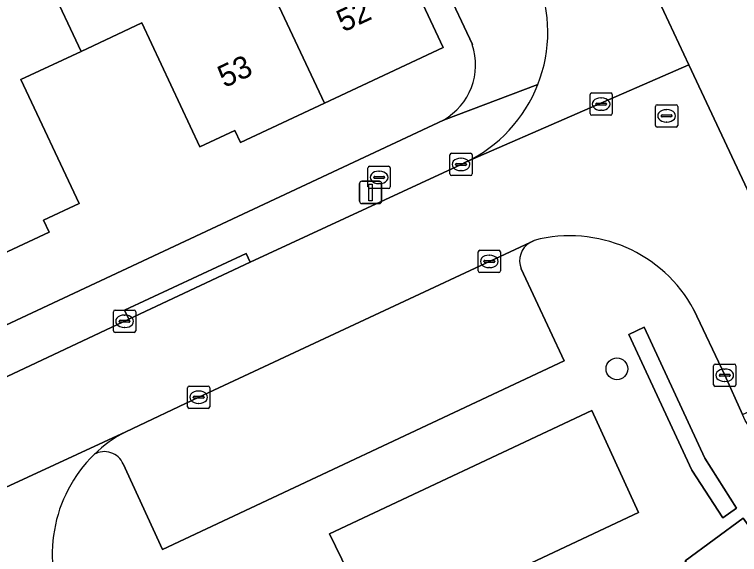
# Model space of a CAD drawing. Extents: x 162879 to 165540, y 384011 to 385181.
# Drawn here: x 163874.48 to 163907.06, y 384315.4 to 384339.68 of the extents above; entities that cross this region are included whole.
import ezdxf

# ---------------------------------------------------------------- set-up
doc = ezdxf.new("R2010")
doc.units = 0
for name, color, linetype in [('IMGEO_Boom', 7, 'Continuous'), ('IMGEO_Brandkraan', 7, 'Continuous'), ('IMGEO_Erf', 7, 'Continuous'), ('IMGEO_Groenvoorziening', 7, 'Continuous'), ('IMGEO_Haag', 7, 'Continuous'), ('IMGEO_Kolk', 7, 'Continuous'), ('IMGEO_Lichtmast', 7, 'Continuous'), ('IMGEO_Pand', 7, 'Continuous'), ('IMGEO_Pand_nummerreeks', 7, 'Continuous'), ('IMGEO_Parkeervlak_open', 7, 'Continuous'), ('IMGEO_Rijbaan_lokaal_gesloten', 7, 'Continuous'), ('IMGEO_Rioolput', 7, 'Continuous'), ('IMGEO_Voetpad_open', 7, 'Continuous')]:
    doc.layers.add(name, color=color, linetype=linetype)

msp = doc.modelspace()

# ---------------------------------------------------------------- linework, layer by layer
at = {"layer": 'IMGEO_Boom'}
msp.add_circle((163901.554, 384323.751), 0.489, dxfattribs=at)
at = {"layer": 'IMGEO_Brandkraan'}
for p, q in [((163890.443, 384332.857), (163891.295, 384332.857)), ((163890.368, 384331.931), (163890.368, 384332.783)), ((163890.856, 384332.637), (163890.881, 384332.637)), ((163891.369, 384332.783), (163891.369, 384331.931)), ((163890.627, 384332.351), (163890.627, 384332.363)), ((163891.065, 384332.314), (163890.667, 384332.314)), ((163890.67, 384332.4), (163891.068, 384332.4)), ((163891.111, 384332.363), (163891.111, 384332.351)), ((163890.879, 384332.077), (163890.854, 384332.077)), ((163891.295, 384331.857), (163890.443, 384331.857))]:
    msp.add_line(p, q, dxfattribs=at)
for points in [[(163890.443, 384332.857), (163891.295, 384332.857)], [(163890.368, 384331.931), (163890.368, 384332.783)], [(163891.369, 384332.783), (163891.369, 384331.931)], [(163891.295, 384331.857), (163890.443, 384331.857)]]:
    msp.add_lwpolyline(points, dxfattribs=at)
for centre, radius, start, end in [((163890.445, 384332.781), 0.0765, 91.552, 178.448), ((163890.445, 384332.781), 0.0765, 91.552, 178.448), ((163891.293, 384332.781), 0.0765, 1.552, 88.448), ((163891.293, 384332.781), 0.0765, 1.552, 88.448), ((163890.667, 384332.36), 0.0403, 85.8775, 175.7526), ((163890.664, 384332.35), 0.0366, 178.938, 274.7102), ((163891.068, 384332.357), 0.043, 264.8664, 352.4533), ((163891.072, 384332.362), 0.0386, 1.7309, 96.639), ((163890.445, 384331.933), 0.0765, 181.552, 268.448), ((163890.445, 384331.933), 0.0765, 181.552, 268.448), ((163891.293, 384331.933), 0.0765, 271.552, 358.448), ((163891.293, 384331.933), 0.0765, 271.552, 358.448)]:
    msp.add_arc(centre, radius, start, end, dxfattribs=at)
for centre, major_axis, ratio, start_param, end_param in [((163890.855, 384332.357), (-0.387, 0.002), 0.722429, 4.712389, 7.853982), ((163890.88, 384332.357), (-0.39, 0.002), 0.717154, 1.570796, 4.712389)]:
    msp.add_ellipse(centre, major_axis=major_axis, ratio=ratio, start_param=start_param, end_param=end_param, dxfattribs=at)
at = {"layer": 'IMGEO_Erf'}
for points in [[(163895.057, 384338.324), (163890.087, 384348.891), (163886.367, 384356.8), (163879.926, 384353.788), (163880.083, 384353.451), (163875.891, 384351.499), (163874.656, 384354.151), (163878.848, 384356.103), (163878.614, 384356.605), (163863.373, 384349.478), (163861.138, 384348.883), (163861.827, 384346.296), (163857.881, 384345.245), (163857.193, 384347.833), (163844.072, 384344.341), (163843.714, 384345.683), (163846.774, 384346.497), (163846.073, 384349.131), (163849.929, 384350.156)], [(163888.982, 384348.374), (163893.752, 384338.19), (163888.413, 384335.69), (163884.645, 384333.926), (163884.391, 384334.47), (163882.806, 384333.727), (163880.198, 384339.298), (163877.472, 384338.021), (163874.764, 384336.753), (163877.382, 384331.186), (163875.787, 384330.441), (163876.041, 384329.897), (163872.318, 384328.154), (163872.102, 384328.053), (163871.848, 384328.597), (163870.707, 384328.063), (163870.961, 384327.518), (163867.129, 384325.724), (163861.777, 384323.218), (163858.915, 384329.331), (163855.03, 384328.471), (163851.161, 384327.615)], [(163863.881, 384320.929), (163893.758, 384334.936)]]:
    msp.add_lwpolyline(points, dxfattribs=at)
msp.add_arc((163892.34, 384337.423), 2.862, 299.6881, 18.3571, dxfattribs=at)
at = {"layer": 'IMGEO_Groenvoorziening'}
for points in [[(163906.317, 384317.059), (163906.927, 384317.485), (163905.499, 384319.74), (163902.771, 384325.619), (163902.093, 384325.298), (163904.927, 384319.193)], [(163906.525, 384312.54), (163909.096, 384314.438), (163907.232, 384317.04), (163904.624, 384315.125)]]:
    msp.add_lwpolyline(points, close=True, dxfattribs=at)
at = {"layer": 'IMGEO_Haag'}
msp.add_lwpolyline([(163906.317, 384317.059), (163906.927, 384317.485), (163905.499, 384319.74), (163902.771, 384325.619), (163902.093, 384325.298), (163904.927, 384319.193)], close=True, dxfattribs=at)
at = {"layer": 'IMGEO_Kolk'}
for p, q in [((163894.048, 384332.514), (163894.048, 384333.366)), ((163894.123, 384333.44), (163894.975, 384333.44)), ((163894.536, 384333.22), (163894.561, 384333.22)), ((163895.049, 384333.366), (163895.049, 384332.514)), ((163894.307, 384332.934), (163894.307, 384332.946)), ((163894.745, 384332.897), (163894.347, 384332.897)), ((163894.35, 384332.983), (163894.748, 384332.983)), ((163894.791, 384332.946), (163894.791, 384332.934)), ((163894.559, 384332.66), (163894.534, 384332.66)), ((163894.975, 384332.44), (163894.123, 384332.44)), ((163895.319, 384328.155), (163895.319, 384329.007)), ((163895.394, 384329.081), (163896.246, 384329.081)), ((163896.32, 384329.007), (163896.32, 384328.155)), ((163895.621, 384328.624), (163896.019, 384328.624)), ((163895.807, 384328.861), (163895.832, 384328.861)), ((163895.578, 384328.575), (163895.578, 384328.587)), ((163896.016, 384328.538), (163895.618, 384328.538)), ((163895.83, 384328.301), (163895.805, 384328.301)), ((163896.062, 384328.587), (163896.062, 384328.575)), ((163896.246, 384328.081), (163895.394, 384328.081)), ((163879.005, 384326.389), (163879.857, 384326.389)), ((163878.93, 384325.463), (163878.93, 384326.315)), ((163879.418, 384326.169), (163879.443, 384326.169)), ((163879.931, 384326.315), (163879.931, 384325.463)), ((163879.189, 384325.883), (163879.189, 384325.895)), ((163879.627, 384325.846), (163879.229, 384325.846)), ((163879.232, 384325.932), (163879.63, 384325.932)), ((163879.673, 384325.895), (163879.673, 384325.883)), ((163879.857, 384325.389), (163879.005, 384325.389)), ((163879.441, 384325.609), (163879.416, 384325.609)), ((163905.897, 384323.036), (163905.897, 384323.888)), ((163905.972, 384323.962), (163906.824, 384323.962)), ((163906.385, 384323.742), (163906.41, 384323.742)), ((163906.898, 384323.888), (163906.898, 384323.036)), ((163906.156, 384323.456), (163906.156, 384323.468)), ((163906.594, 384323.419), (163906.196, 384323.419)), ((163906.199, 384323.505), (163906.597, 384323.505)), ((163906.64, 384323.468), (163906.64, 384323.456)), ((163906.408, 384323.182), (163906.383, 384323.182)), ((163882.259, 384322.049), (163882.259, 384322.901)), ((163882.334, 384322.975), (163883.186, 384322.975)), ((163882.747, 384322.755), (163882.772, 384322.755)), ((163883.26, 384322.901), (163883.26, 384322.049)), ((163906.824, 384322.962), (163905.972, 384322.962)), ((163882.518, 384322.469), (163882.518, 384322.481)), ((163882.956, 384322.432), (163882.558, 384322.432)), ((163882.561, 384322.518), (163882.959, 384322.518)), ((163883.002, 384322.481), (163883.002, 384322.469)), ((163882.77, 384322.195), (163882.745, 384322.195)), ((163883.186, 384321.975), (163882.334, 384321.975))]:
    msp.add_line(p, q, dxfattribs=at)
for points in [[(163894.048, 384332.514), (163894.048, 384333.366)], [(163894.123, 384333.44), (163894.975, 384333.44)], [(163895.049, 384333.366), (163895.049, 384332.514)], [(163894.975, 384332.44), (163894.123, 384332.44)], [(163895.319, 384328.155), (163895.319, 384329.007)], [(163895.394, 384329.081), (163896.246, 384329.081)], [(163896.32, 384329.007), (163896.32, 384328.155)], [(163896.246, 384328.081), (163895.394, 384328.081)], [(163879.005, 384326.389), (163879.857, 384326.389)], [(163878.93, 384325.463), (163878.93, 384326.315)], [(163879.931, 384326.315), (163879.931, 384325.463)], [(163879.857, 384325.389), (163879.005, 384325.389)], [(163905.897, 384323.036), (163905.897, 384323.888)], [(163905.972, 384323.962), (163906.824, 384323.962)], [(163906.898, 384323.888), (163906.898, 384323.036)], [(163882.259, 384322.049), (163882.259, 384322.901)], [(163882.334, 384322.975), (163883.186, 384322.975)], [(163883.26, 384322.901), (163883.26, 384322.049)], [(163906.824, 384322.962), (163905.972, 384322.962)], [(163883.186, 384321.975), (163882.334, 384321.975)]]:
    msp.add_lwpolyline(points, dxfattribs=at)
for centre, radius, start, end in [((163894.125, 384333.364), 0.0765, 91.552, 178.448), ((163894.125, 384333.364), 0.0765, 91.552, 178.448), ((163894.973, 384333.364), 0.0765, 1.552, 88.448), ((163894.973, 384333.364), 0.0765, 1.552, 88.448), ((163894.347, 384332.943), 0.0403, 85.8775, 175.7526), ((163894.344, 384332.933), 0.0366, 178.938, 274.7102), ((163894.748, 384332.94), 0.043, 264.8664, 352.4533), ((163894.752, 384332.945), 0.0386, 1.7309, 96.639), ((163894.125, 384332.516), 0.0765, 181.552, 268.448), ((163894.125, 384332.516), 0.0765, 181.552, 268.448), ((163894.973, 384332.516), 0.0765, 271.552, 358.448), ((163894.973, 384332.516), 0.0765, 271.552, 358.448), ((163895.396, 384329.005), 0.0765, 91.552, 178.448), ((163895.396, 384329.005), 0.0765, 91.552, 178.448), ((163896.244, 384329.005), 0.0765, 1.552, 88.448), ((163896.244, 384329.005), 0.0765, 1.552, 88.448), ((163895.618, 384328.584), 0.0403, 85.8775, 175.7526), ((163896.023, 384328.586), 0.0386, 1.7309, 96.639), ((163895.615, 384328.574), 0.0366, 178.938, 274.7102), ((163896.019, 384328.581), 0.043, 264.8664, 352.4533), ((163895.396, 384328.157), 0.0765, 181.552, 268.448), ((163895.396, 384328.157), 0.0765, 181.552, 268.448), ((163896.244, 384328.157), 0.0765, 271.552, 358.448), ((163896.244, 384328.157), 0.0765, 271.552, 358.448), ((163879.007, 384326.313), 0.0765, 91.552, 178.448), ((163879.007, 384326.313), 0.0765, 91.552, 178.448), ((163879.855, 384326.313), 0.0765, 1.552, 88.448), ((163879.855, 384326.313), 0.0765, 1.552, 88.448), ((163879.229, 384325.892), 0.0403, 85.8775, 175.7526), ((163879.226, 384325.882), 0.0366, 178.938, 274.7102), ((163879.63, 384325.889), 0.043, 264.8664, 352.4533), ((163879.634, 384325.894), 0.0386, 1.7309, 96.639), ((163879.007, 384325.465), 0.0765, 181.552, 268.448), ((163879.007, 384325.465), 0.0765, 181.552, 268.448), ((163879.855, 384325.465), 0.0765, 271.552, 358.448), ((163879.855, 384325.465), 0.0765, 271.552, 358.448), ((163905.974, 384323.886), 0.0765, 91.552, 178.448), ((163905.974, 384323.886), 0.0765, 91.552, 178.448), ((163906.822, 384323.886), 0.0765, 1.552, 88.448), ((163906.822, 384323.886), 0.0765, 1.552, 88.448), ((163906.196, 384323.465), 0.0403, 85.8775, 175.7526), ((163906.193, 384323.455), 0.0366, 178.938, 274.7102), ((163906.597, 384323.462), 0.043, 264.8664, 352.4533), ((163906.601, 384323.467), 0.0386, 1.7309, 96.639), ((163882.336, 384322.899), 0.0765, 91.552, 178.448), ((163882.336, 384322.899), 0.0765, 91.552, 178.448), ((163883.184, 384322.899), 0.0765, 1.552, 88.448), ((163883.184, 384322.899), 0.0765, 1.552, 88.448), ((163905.974, 384323.038), 0.0765, 181.552, 268.448), ((163905.974, 384323.038), 0.0765, 181.552, 268.448), ((163906.822, 384323.038), 0.0765, 271.552, 358.448), ((163906.822, 384323.038), 0.0765, 271.552, 358.448), ((163882.558, 384322.478), 0.0403, 85.8775, 175.7526), ((163882.555, 384322.468), 0.0366, 178.938, 274.7102), ((163882.959, 384322.475), 0.043, 264.8664, 352.4533), ((163882.963, 384322.48), 0.0386, 1.7309, 96.639), ((163882.336, 384322.051), 0.0765, 181.552, 268.448), ((163882.336, 384322.051), 0.0765, 181.552, 268.448), ((163883.184, 384322.051), 0.0765, 271.552, 358.448), ((163883.184, 384322.051), 0.0765, 271.552, 358.448)]:
    msp.add_arc(centre, radius, start, end, dxfattribs=at)
for centre, major_axis, ratio, start_param, end_param in [((163894.535, 384332.94), (-0.387, 0.002), 0.722429, 4.712389, 7.853982), ((163894.56, 384332.94), (-0.39, 0.002), 0.717154, 1.570796, 4.712389), ((163895.806, 384328.581), (-0.387, 0.002), 0.722429, 4.712389, 7.853982), ((163895.831, 384328.581), (-0.39, 0.002), 0.717154, 1.570796, 4.712389), ((163879.417, 384325.889), (-0.387, 0.002), 0.722429, 4.712389, 7.853982), ((163879.442, 384325.889), (-0.39, 0.002), 0.717154, 1.570796, 4.712389), ((163906.384, 384323.462), (-0.387, 0.002), 0.722429, 4.712389, 7.853982), ((163906.409, 384323.462), (-0.39, 0.002), 0.717154, 1.570796, 4.712389), ((163882.746, 384322.475), (-0.387, 0.002), 0.722429, 4.712389, 7.853982), ((163882.771, 384322.475), (-0.39, 0.002), 0.717154, 1.570796, 4.712389)]:
    msp.add_ellipse(centre, major_axis=major_axis, ratio=ratio, start_param=start_param, end_param=end_param, dxfattribs=at)
at = {"layer": 'IMGEO_Lichtmast'}
for p, q in [((163889.99, 384331.282), (163889.99, 384332.082)), ((163889.99, 384332.082), (163889.99, 384331.282)), ((163890.09, 384332.182), (163890.88, 384332.182)), ((163890.88, 384332.182), (163890.09, 384332.182)), ((163890.98, 384332.082), (163890.98, 384331.282)), ((163890.98, 384331.282), (163890.98, 384332.082)), ((163890.88, 384331.182), (163890.09, 384331.182)), ((163890.09, 384331.182), (163890.88, 384331.182))]:
    msp.add_line(p, q, dxfattribs=at)
msp.add_lwpolyline([(163890.41, 384332.057), (163890.56, 384332.057), (163890.56, 384331.307), (163890.41, 384331.307), (163890.41, 384332.057)], dxfattribs=at)
for centre, start, end in [((163890.09, 384332.082), 90, 180), ((163890.09, 384332.082), 90, 180), ((163890.88, 384332.082), 0, 90), ((163890.88, 384332.082), 360, 90), ((163890.09, 384331.282), 180, 270), ((163890.09, 384331.282), 180, 270), ((163890.88, 384331.282), 270, 0), ((163890.88, 384331.282), 270, 0)]:
    msp.add_arc(centre, 0.1, start, end, dxfattribs=at)
at = {"layer": 'IMGEO_Pand'}
for points in [[(163883.635, 384345.871), (163888.413, 384335.69), (163893.752, 384338.19), (163888.982, 384348.374)], [(163883.635, 384345.871), (163878.595, 384343.511), (163877.603, 384345.631), (163874.574, 384344.201), (163877.472, 384338.021), (163880.198, 384339.298), (163882.806, 384333.727), (163884.391, 384334.47), (163884.645, 384333.926), (163888.413, 384335.69)], [(163874.574, 384344.201), (163873.082, 384343.496), (163871.581, 384342.787), (163872.569, 384340.676), (163867.481, 384338.294), (163872.318, 384328.154), (163876.041, 384329.897), (163875.787, 384330.441), (163877.382, 384331.186), (163874.764, 384336.753), (163877.472, 384338.021)]]:
    msp.add_lwpolyline(points, close=True, dxfattribs=at)
at = {"layer": 'IMGEO_Parkeervlak_open'}
for points in [[(163901.984, 384343.392), (163902.988, 384341.269), (163904.789, 384337.423), (163909.236, 384327.925), (163910.322, 384325.67)], [(163897.648, 384329.434), (163882.76, 384322.477), (163879.48, 384320.926)], [(163899.184, 384324.113), (163897.25, 384328.244)], [(163879.371, 384319.475), (163881.139, 384315.623), (163899.184, 384324.113)]]:
    msp.add_lwpolyline(points, dxfattribs=at)
msp.add_lwpolyline([(163902.519, 384317.29), (163900.421, 384321.874), (163888.639, 384316.337), (163890.843, 384311.814), (163891.043, 384311.908), (163896.954, 384314.676)], close=True, dxfattribs=at)
for centre, radius, start, end in [((163898.152, 384328.604), 0.971, 121.2584, 201.7562), ((163882.321, 384315.48), 6.142, 117.5528, 133.8889), ((163878.522, 384319.1), 0.929, 23.8404, 119.6054)]:
    msp.add_arc(centre, radius, start, end, dxfattribs=at)
at = {"layer": 'IMGEO_Rijbaan_lokaal_gesloten'}
for points in [[(163894.751, 384333.036), (163904.789, 384337.423), (163902.988, 384341.269), (163901.984, 384343.392), (163900.594, 384346.351), (163896.753, 384354.528), (163894.159, 384360.171), (163886.822, 384375.777)], [(163905.016, 384326.406), (163906.399, 384323.462), (163907.197, 384321.691), (163911.307, 384323.588), (163910.322, 384325.67), (163909.236, 384327.925), (163904.789, 384337.423), (163894.751, 384333.036), (163894.549, 384332.939), (163885.076, 384328.543), (163879.615, 384325.991), (163863.997, 384318.625), (163861.94, 384317.777), (163861.247, 384317.522)], [(163879.48, 384320.926), (163882.76, 384322.477), (163897.648, 384329.434), (163897.842, 384329.525)], [(163862.135, 384313.051), (163863.528, 384313.607), (163863.746, 384313.708), (163864.258, 384313.87), (163879.48, 384320.926)], [(163879.48, 384320.926), (163864.258, 384313.87)]]:
    msp.add_lwpolyline(points, dxfattribs=at)
for centre, radius, start, end in [((163891.953, 384338.895), 6.495, 338.7146, 21.8849), ((163891.958, 384338.894), 6.49, 295.4874, 338.7008), ((163899.442, 384323.395), 6.335, 28.3756, 104.629), ((163882.321, 384315.48), 6.142, 117.5528, 133.8889), ((163882.458, 384315.425), 6.277, 134.4361, 205.7719)]:
    msp.add_arc(centre, radius, start, end, dxfattribs=at)
at = {"layer": 'IMGEO_Rioolput'}
for p, q in [((163900.421, 384336.152), (163901.273, 384336.152)), ((163900.346, 384335.226), (163900.346, 384336.078)), ((163900.834, 384335.932), (163900.859, 384335.932)), ((163901.347, 384336.078), (163901.347, 384335.226)), ((163900.605, 384335.646), (163900.605, 384335.658)), ((163901.043, 384335.609), (163900.645, 384335.609)), ((163900.648, 384335.695), (163901.046, 384335.695)), ((163901.089, 384335.658), (163901.089, 384335.646)), ((163903.286, 384334.696), (163903.286, 384335.548)), ((163903.361, 384335.622), (163904.213, 384335.622)), ((163904.287, 384335.548), (163904.287, 384334.696)), ((163901.273, 384335.152), (163900.421, 384335.152)), ((163900.857, 384335.372), (163900.832, 384335.372)), ((163903.545, 384335.116), (163903.545, 384335.128)), ((163903.588, 384335.165), (163903.986, 384335.165)), ((163903.774, 384335.402), (163903.799, 384335.402)), ((163904.029, 384335.128), (163904.029, 384335.116)), ((163903.983, 384335.079), (163903.585, 384335.079)), ((163903.797, 384334.842), (163903.772, 384334.842)), ((163904.213, 384334.622), (163903.361, 384334.622))]:
    msp.add_line(p, q, dxfattribs=at)
for points in [[(163900.421, 384336.152), (163901.273, 384336.152)], [(163900.346, 384335.226), (163900.346, 384336.078)], [(163901.347, 384336.078), (163901.347, 384335.226)], [(163903.286, 384334.696), (163903.286, 384335.548)], [(163903.361, 384335.622), (163904.213, 384335.622)], [(163904.287, 384335.548), (163904.287, 384334.696)], [(163901.273, 384335.152), (163900.421, 384335.152)], [(163904.213, 384334.622), (163903.361, 384334.622)]]:
    msp.add_lwpolyline(points, dxfattribs=at)
for centre, radius, start, end in [((163900.423, 384336.076), 0.0765, 91.552, 178.448), ((163900.423, 384336.076), 0.0765, 91.552, 178.448), ((163901.271, 384336.076), 0.0765, 1.552, 88.448), ((163901.271, 384336.076), 0.0765, 1.552, 88.448), ((163900.645, 384335.655), 0.0403, 85.8775, 175.7526), ((163900.642, 384335.645), 0.0366, 178.938, 274.7102), ((163901.046, 384335.652), 0.043, 264.8664, 352.4533), ((163901.05, 384335.657), 0.0386, 1.7309, 96.639), ((163903.363, 384335.546), 0.0765, 91.552, 178.448), ((163903.363, 384335.546), 0.0765, 91.552, 178.448), ((163904.211, 384335.546), 0.0765, 1.552, 88.448), ((163904.211, 384335.546), 0.0765, 1.552, 88.448), ((163900.423, 384335.228), 0.0765, 181.552, 268.448), ((163900.423, 384335.228), 0.0765, 181.552, 268.448), ((163901.271, 384335.228), 0.0765, 271.552, 358.448), ((163901.271, 384335.228), 0.0765, 271.552, 358.448), ((163903.585, 384335.125), 0.0403, 85.8775, 175.7526), ((163903.99, 384335.127), 0.0386, 1.7309, 96.639), ((163903.582, 384335.115), 0.0366, 178.938, 274.7102), ((163903.986, 384335.122), 0.043, 264.8664, 352.4533), ((163903.363, 384334.698), 0.0765, 181.552, 268.448), ((163903.363, 384334.698), 0.0765, 181.552, 268.448), ((163904.211, 384334.698), 0.0765, 271.552, 358.448), ((163904.211, 384334.698), 0.0765, 271.552, 358.448)]:
    msp.add_arc(centre, radius, start, end, dxfattribs=at)
for centre, major_axis, ratio, start_param, end_param in [((163900.833, 384335.652), (-0.387, 0.002), 0.722429, 4.712389, 7.853982), ((163900.858, 384335.652), (-0.39, 0.002), 0.717154, 1.570796, 4.712389), ((163903.773, 384335.122), (-0.387, 0.002), 0.722429, 4.712389, 7.853982), ((163903.798, 384335.122), (-0.39, 0.002), 0.717154, 1.570796, 4.712389)]:
    msp.add_ellipse(centre, major_axis=major_axis, ratio=ratio, start_param=start_param, end_param=end_param, dxfattribs=at)
at = {"layer": 'IMGEO_Voetpad_open'}
for points in [[(163875.505, 384380.136), (163880.548, 384369.283), (163883.096, 384363.799), (163884.423, 384360.973), (163885.055, 384359.617), (163886.367, 384356.8), (163890.087, 384348.891), (163895.057, 384338.324)], [(163898.005, 384336.537), (163893.758, 384334.936), (163863.881, 384320.929)], [(163893.758, 384334.936), (163898.005, 384336.537)], [(163861.087, 384317.944), (163861.247, 384317.522), (163861.94, 384317.777), (163863.997, 384318.625), (163879.615, 384325.991), (163879.432, 384326.389), (163884.898, 384328.932), (163885.076, 384328.543), (163894.549, 384332.939), (163894.751, 384333.036)], [(163897.842, 384329.525), (163897.648, 384329.434)], [(163897.25, 384328.244), (163899.184, 384324.113), (163881.139, 384315.623), (163879.371, 384319.475)], [(163920.218, 384302.66), (163915.448, 384309.442), (163915.144, 384309.904), (163914.237, 384309.242), (163909.693, 384315.856), (163910.606, 384316.457), (163907.32, 384321.427), (163907.197, 384321.691), (163906.399, 384323.462), (163905.016, 384326.406)]]:
    msp.add_lwpolyline(points, dxfattribs=at)
for points in [[(163885.076, 384328.543), (163884.898, 384328.932), (163879.432, 384326.389), (163879.615, 384325.991)], [(163906.317, 384317.059), (163904.927, 384319.193), (163902.093, 384325.298), (163902.771, 384325.619), (163905.499, 384319.74), (163906.927, 384317.485)], [(163890.75, 384300.683), (163886.492, 384309.76), (163890.843, 384311.814), (163888.639, 384316.337), (163900.421, 384321.874), (163902.519, 384317.29), (163896.954, 384314.676), (163891.043, 384311.908), (163893.092, 384307.566), (163895.293, 384302.867)], [(163906.525, 384312.54), (163904.624, 384315.125), (163907.232, 384317.04), (163909.096, 384314.438)]]:
    msp.add_lwpolyline(points, close=True, dxfattribs=at)
for centre, radius, start, end in [((163891.953, 384338.895), 6.495, 338.7146, 21.8849), ((163892.34, 384337.423), 2.862, 299.6881, 18.3571), ((163891.958, 384338.894), 6.49, 295.4874, 338.7008), ((163899.442, 384323.395), 6.335, 28.3756, 104.629), ((163898.152, 384328.604), 0.971, 121.2584, 201.7562), ((163882.458, 384315.425), 6.277, 134.4361, 205.7719), ((163878.522, 384319.1), 0.929, 23.8404, 119.6054)]:
    msp.add_arc(centre, radius, start, end, dxfattribs=at)

# ---------------------------------------------------------------- texts
at = {"layer": 'IMGEO_Pand_nummerreeks'}
for s, p in [('52', (163889.259, 384338.869)), ('53', (163883.916, 384336.367))]:
    msp.add_text(s, height=1, rotation=25.0895, dxfattribs=at).set_placement(p)

doc.saveas('drawing.dxf')
